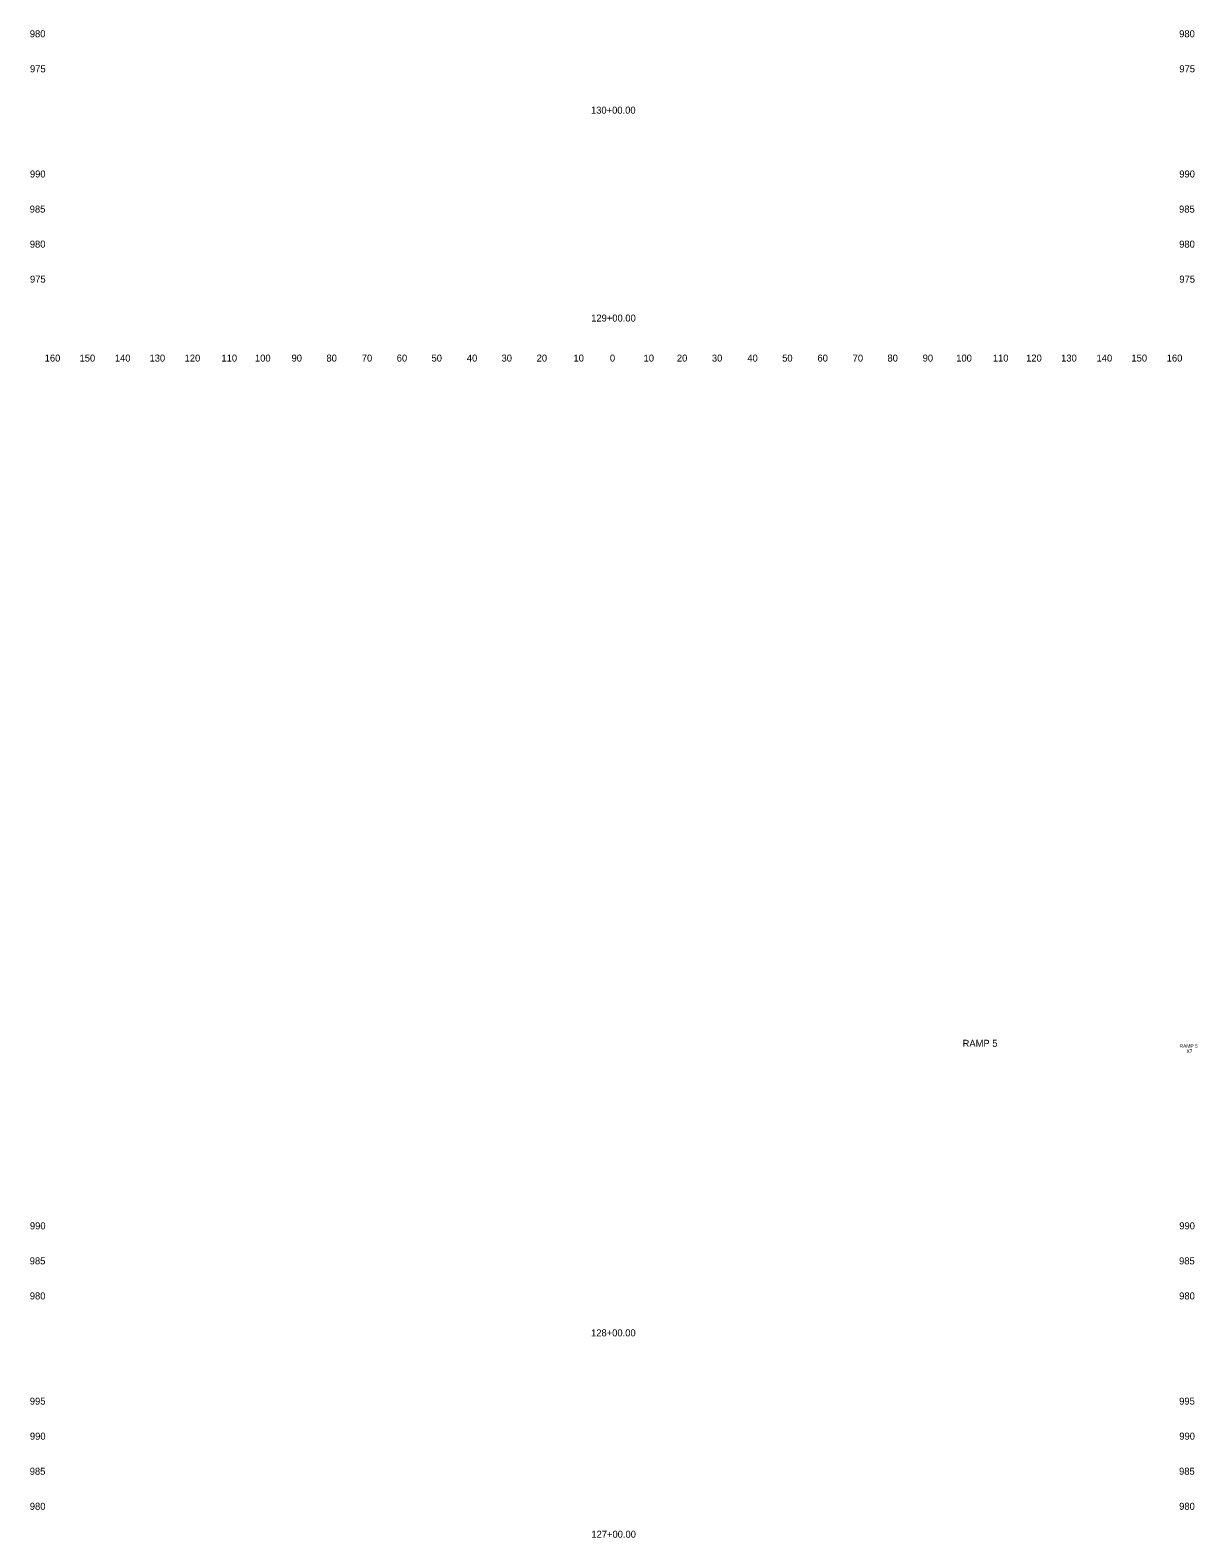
# Model space of a CAD drawing. Extents: x 4994 to 5842, y 4997 to 8804.
# Drawn here: x 4994 to 5326.7, y 7462 to 7892 of the extents above; entities that cross this region are included whole.
import ezdxf

# ---------------------------------------------------------------- set-up
doc = ezdxf.new("R2010")
doc.units = 0
for name, color, linetype in [('CLS_Search_Dist', 7, 'Continuous'), ('RD_XE_Ground', 7, 'Continuous'), ('UC_PD_Text', 7, 'Continuous')]:
    doc.layers.add(name, color=color, linetype=linetype)

msp = doc.modelspace()

# ---------------------------------------------------------------- texts
at = {"layer": 'CLS_Search_Dist'}
for s, p in [('980', (4993.86, 7890)), ('980', (5321.66, 7890)), ('975', (4993.91, 7880)), ('975', (5321.71, 7880)), ('990', (4993.89, 7850)), ('990', (5321.69, 7850)), ('985', (4993.83, 7840)), ('985', (5321.63, 7840)), ('980', (4993.86, 7830)), ('980', (5321.66, 7830)), ('975', (4993.91, 7820)), ('975', (5321.71, 7820)), ('160', (4998.1, 7797.5)), ('150', (5008.04, 7797.5)), ('140', (5018.1, 7797.5)), ('130', (5027.99, 7797.5)), ('120', (5038.01, 7797.5)), ('110', (5048.51, 7797.5)), ('100', (5058.07, 7797.5)), ('90', (5068.5, 7797.5)), ('80', (5078.46, 7797.5)), ('70', (5088.54, 7797.5)), ('60', (5098.5, 7797.5)), ('50', (5108.43, 7797.5)), ('40', (5118.5, 7797.5)), ('30', (5128.39, 7797.5)), ('20', (5138.4, 7797.5)), ('10', (5148.91, 7797.5)), ('0', (5159.3, 7797.5)), ('0', (5159.3, 7797.5)), ('10', (5168.91, 7797.5)), ('20', (5178.4, 7797.5)), ('30', (5188.39, 7797.5)), ('40', (5198.5, 7797.5)), ('50', (5208.43, 7797.5)), ('60', (5218.5, 7797.5)), ('70', (5228.54, 7797.5)), ('80', (5238.46, 7797.5)), ('90', (5248.5, 7797.5)), ('100', (5258.07, 7797.5)), ('110', (5268.51, 7797.5)), ('120', (5278.01, 7797.5)), ('130', (5287.99, 7797.5)), ('140', (5298.1, 7797.5)), ('150', (5308.04, 7797.5)), ('160', (5318.1, 7797.5)), ('990', (4993.89, 7550)), ('990', (5321.69, 7550)), ('985', (4993.83, 7540)), ('985', (5321.63, 7540)), ('980', (4993.86, 7530)), ('980', (5321.66, 7530)), ('995', (4993.86, 7500)), ('995', (5321.66, 7500)), ('990', (4993.89, 7490)), ('990', (5321.69, 7490)), ('985', (4993.83, 7480)), ('985', (5321.63, 7480)), ('980', (4993.86, 7470)), ('980', (5321.66, 7470))]:
    msp.add_text(s, height=2, dxfattribs=at).set_placement(p)
at = {"layer": 'RD_XE_Ground'}
for s, p in [('130+00.00', (5153.91, 7868.22)), ('129+00.00', (5153.96, 7808.91)), ('128+00.00', (5153.93, 7519.47)), ('127+00.00', (5154.01, 7462.03))]:
    msp.add_text(s, height=2, dxfattribs=at).set_placement(p)
at = {"layer": 'UC_PD_Text'}
for s, height, p in [('RAMP 5', 2, (5259.89, 7602.06)), ('RAMP 5', 1, (5321.78, 7601.8)), ('X7', 1, (5323.74, 7600.3))]:
    msp.add_text(s, height=height, dxfattribs=at).set_placement(p)

doc.saveas('drawing.dxf')
